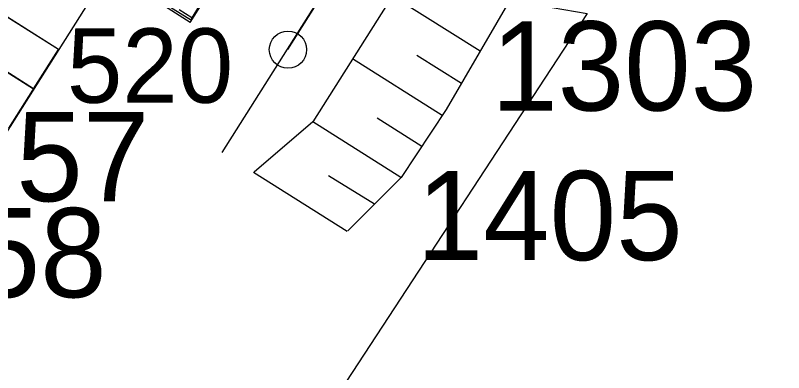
# Model space of a CAD drawing. Extents: x -743546 to -74, y -1128126 to -103.
# Drawn here: x -743179.3 to -743168.98, y -1127109.43 to -1127104.62 of the extents above; entities that cross this region are included whole.
import ezdxf

# ---------------------------------------------------------------- set-up
doc = ezdxf.new("R2010")
doc.units = 0
for name, color, linetype in [('_SVAH - Přesunutá', 7, 'Continuous'), ('_Zabezpečovací zařízení', 7, 'Continuous'), ('KOL_ROST', 7, 'Continuous'), ('křížky', 7, 'Continuous'), ('OSA', 7, 'Continuous'), ('SMER_VYS_VYROVNANI', 7, 'Continuous'), ('TRATIVOD', 7, 'Continuous'), ('Vrstva 53', 7, 'Continuous'), ('Vrstva 60', 7, 'Continuous')]:
    doc.layers.add(name, color=color, linetype=linetype)

# ---------------------------------------------------------------- blocks, each defined once
blk = doc.blocks.new('POINT_DISPLAY')
blk.add_line((0, 0), (0, 0))

msp = doc.modelspace()

# ---------------------------------------------------------------- linework, layer by layer
at = {"layer": '_SVAH - Přesunutá'}
for p, q in [((-743173.059, -1127105.107), (-743174.235, -1127104.364)), ((-743173.565, -1127105.97), (-743174.769, -1127105.21)), ((-743173.309, -1127105.54), (-743173.906, -1127105.163)), ((-743174.12, -1127106.803), (-743175.303, -1127106.055)), ((-743173.842, -1127106.386), (-743174.439, -1127106.009)), ((-743174.842, -1127107.529), (-743176.097, -1127106.736)), ((-743174.477, -1127107.163), (-743175.091, -1127106.782))]:
    msp.add_line(p, q, dxfattribs=at)
for points in [[(-743173.338, -1127101.419), (-743176.524, -1127106.467)], [(-743172.435, -1127101.512), (-743175.303, -1127106.055), (-743176.091, -1127106.731)], [(-743172.596, -1127104.307), (-743173.512, -1127105.891), (-743174.119, -1127106.803), (-743174.835, -1127107.522)]]:
    msp.add_lwpolyline(points, dxfattribs=at)
at = {"layer": '_Zabezpečovací zařízení'}
for p, q in [((-743178.716, -1127105.083), (-743179.773, -1127104.416)), ((-743179.05, -1127105.611), (-743180.107, -1127104.945)), ((-743179.383, -1127106.14), (-743178.716, -1127105.083))]:
    msp.add_line(p, q, dxfattribs=at)
msp.add_lwpolyline([(-743179.773, -1127104.416), (-743180.107, -1127104.945), (-743179.05, -1127105.611), (-743178.716, -1127105.083), (-743179.773, -1127104.416)], dxfattribs=at)
at = {"layer": 'KOL_ROST'}
for p, q in [((-743176.949, -1127104.72), (-743177.344, -1127104.471)), ((-743176.932, -1127104.692), (-743177.328, -1127104.446)), ((-743176.949, -1127104.72), (-743176.789, -1127104.467)), ((-743176.836, -1127104.511), (-743176.929, -1127104.659)), ((-743176.929, -1127104.659), (-743177.098, -1127104.552)), ((-743176.934, -1127104.697), (-743176.929, -1127104.659))]:
    msp.add_line(p, q, dxfattribs=at)
at = {"layer": 'OSA'}
msp.add_lwpolyline([(-743169.53, -1127090.542), (-743178.712, -1127105.086)], dxfattribs=at)
at = {"layer": 'SMER_VYS_VYROVNANI'}
msp.add_lwpolyline([(-743178.712, -1127105.086), (-743197.526, -1127134.888)], dxfattribs=at)
at = {"layer": 'TRATIVOD'}
msp.add_lwpolyline([(-743175.637, -1127105.086), (-743168.399, -1127093.621), (-743157.384, -1127076.172), (-743151.775, -1127072.311)], dxfattribs=at)
msp.add_circle((-743175.637, -1127105.086), 0.25, dxfattribs=at)
at = {"layer": 'Vrstva 53'}
msp.add_lwpolyline([(-743183.34, -1127102.57), (-743171.62, -1127104.6), (-743183.01, -1127122.02), (-743195.51, -1127141.13), (-743203.92, -1127154.43), (-743215.95, -1127172.74), (-743210.36, -1127174.02), (-743237.28, -1127205.49), (-743245.75, -1127220.06), (-743259.48, -1127245.93)], dxfattribs=at)
at = {"layer": 'Vrstva 60'}
msp.add_line((-743175.637, -1127105.086), (-743175.637, -1127105.086), dxfattribs=at)

# ---------------------------------------------------------------- block references
at = {"layer": 'křížky', "xscale": 10, "yscale": 10, "rotation": 61.14491455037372}
msp.add_blockref('POINT_DISPLAY', (-743175.637, -1127105.086), dxfattribs=at)

# ---------------------------------------------------------------- texts
at = {"layer": 'Vrstva 60'}
for s, height, p in [('1303', 1.2, (-743172.909, -1127105.905)), ('520', 1, (-743178.603, -1127105.8)), ('57', 1.2, (-743179.283, -1127107.124)), ('1405', 1.2, (-743173.909, -1127107.916)), ('58', 1.2, (-743179.855, -1127108.415))]:
    msp.add_text(s, height=height, dxfattribs=at).set_placement(p)

doc.saveas('drawing.dxf')
